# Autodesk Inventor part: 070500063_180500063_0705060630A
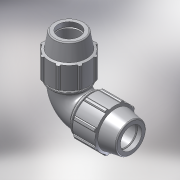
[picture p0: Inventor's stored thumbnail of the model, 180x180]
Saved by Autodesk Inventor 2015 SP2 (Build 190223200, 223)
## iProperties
Created: 2017-02
Part Number: 070500063_180500063_0705060630A
Material: PVC-Piping
Description: PLASSON 90° ELBOW 63-63
Document SubType Name: Modeling
Designer: KIM
Mass: 92.6774 g
Surface Area: 199.44 cm^2
Volume: 66.1981 cm^3
Density: 1.4 g/cm^3
Appearance: Smooth - White
Author: KIM
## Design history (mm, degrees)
derived "07050.ipt"
feature "Solid1::07050.ipt"
tag "TaggingFeature1"
body "Solid1"
other parameters: "d2" = 63, "d4" = 12.58333, "d5" = 37.75, "d7" = 113, "d9" = 21.57143, "d11" = 5.03333, "d13" = 120 deg, "d14" = 81.9, "d15" = 10 deg, "d16" = 98.31, "d18" = 3.15, "d19" = 35 deg, "d20" = 17.5 deg, "d21" = 105.09, "d23" = 0, "d25" = 360 deg, "d27" = 2.26, "d33" = 1.26, "d42" = 55.87, "d43" = 3.39, "d46" = 1.89, "d51" = 151, "d59" = 90 deg, "d64" = 56.7, "d67" = 84.75, "d68" = 2.51667, "d70" = 90 deg, "d71" = 9.45, "d_" = 63, "E_" = 113, "A_" = 151
